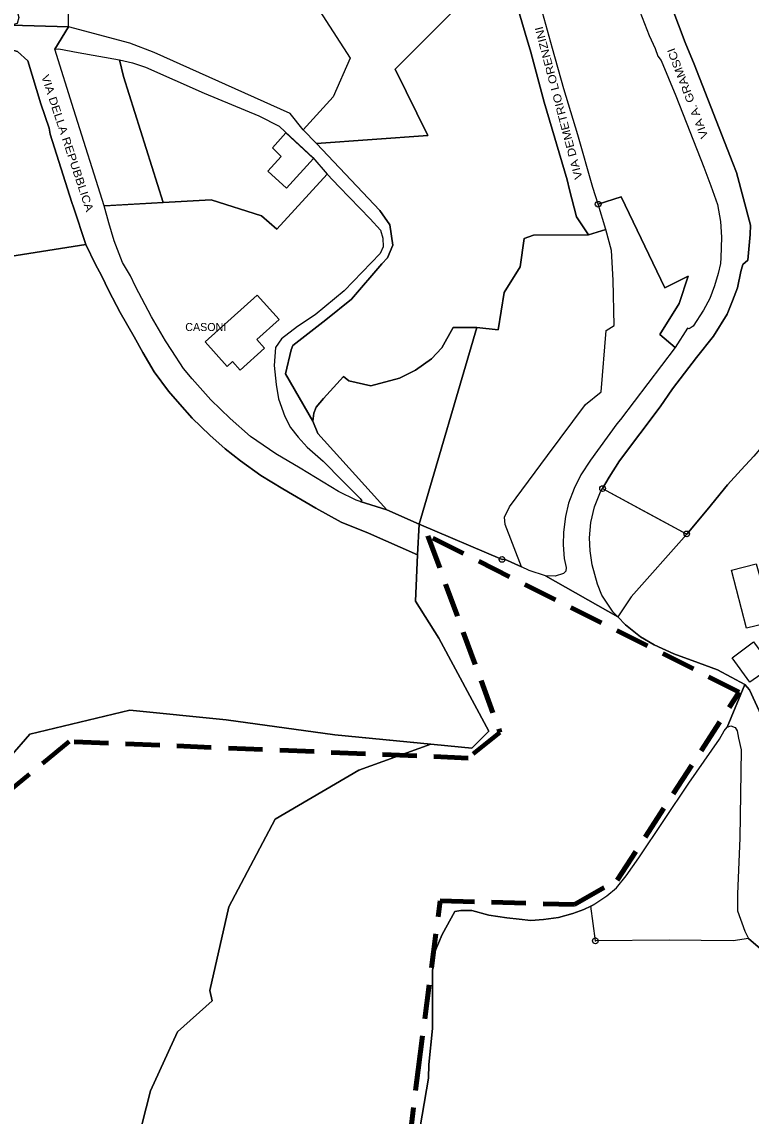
# Model space of a CAD drawing. Extents: x 654952 to 658955, y 890426 to 894481.
# Drawn here: x 657629.2 to 657884.3, y 891148.5 to 891531.5 of the extents above; entities that cross this region are included whole.
import ezdxf

# ---------------------------------------------------------------- set-up
doc = ezdxf.new("R2010")
doc.units = 0
doc.header["$LTSCALE"] = 4
doc.header["$PDMODE"] = 32
doc.header["$PDSIZE"] = 2
doc.linetypes.add('MEDIUM_DASHED', pattern=[4.5, 3, -1.5])
for name, color, linetype, lineweight in [('1', 7, 'Continuous', 25), ('11', 7, 'Continuous', 25), ('14', 7, 'Continuous', 25), ('17', 7, 'Continuous', 25), ('19', 7, 'Continuous', 25), ('36', 7, 'Continuous', 25), ('4', 7, 'Continuous', 25), ('5', 7, 'Continuous', 25), ('55', 7, 'Continuous', 25), ('56', 7, 'Continuous', 25), ('6', 7, 'Continuous', 25), ('7', 7, 'MEDIUM_DASHED', 100), ('9', 7, 'Continuous', 25)]:
    doc.layers.add(name, color=color, linetype=linetype, lineweight=lineweight)
doc.layers.add('58', color=7, linetype='Continuous')

msp = doc.modelspace()

# ---------------------------------------------------------------- linework, layer by layer
at = {"layer": '1'}
msp.add_line((657695.42, 891469.27), (657678.6, 891468.31), dxfattribs=at)
for points in [[(657678.6, 891468.31), (657664.76, 891512.47), (657663.34, 891518.26)], [(657663.34, 891518.26), (657667.91, 891517.26), (657672.42, 891515.71), (657692.92, 891506.62), (657712.15, 891498.68), (657719.21, 891495.02), (657721.27, 891493.05), (657730.99, 891484.02), (657736.01, 891478.21), (657718.39, 891458.96)], [(657953.49, 891476.31), (657955.21, 891471.7), (657956.89, 891451.72), (657957.48, 891438.11), (657957.77, 891432.29), (657956.5, 891430.66), (657954.45, 891430.79), (657949.69, 891426.24), (657930.35, 891404.21), (657925.88, 891406.29), (657918.64, 891416.53), (657907.61, 891404.82), (657900.08, 891396.93), (657885.32, 891379.52), (657880.83, 891374.69), (657876.1, 891369.48), (657868.99, 891360.8), (657861.85, 891352.23), (657842.43, 891330.3), (657837.7, 891323.26)], [(657718.39, 891458.96), (657713.01, 891463.69), (657695.42, 891469.27)], [(657837.7, 891323.26), (657840.4, 891320.51), (657845.62, 891316.26), (657850.47, 891313.45), (657857.34, 891310.34), (657865.89, 891307.18), (657872.64, 891304.78), (657879.11, 891301.28), (657882.13, 891299.62), (657883.82, 891297.74), (657888.48, 891287.53), (657889.08, 891285.16), (657888.12, 891269.81), (657887.77, 891267.8)]]:
    msp.add_lwpolyline(points, dxfattribs=at)
msp.add_lwpolyline([(657721.5, 891492.72), (657716.87, 891487.48), (657719.94, 891484.48), (657715.24, 891479.24), (657721.75, 891473.36), (657731.22, 891483.7)], close=True, dxfattribs=at)
at = {"layer": '11'}
for points in [[(657612.44, 891525.06), (657603.45, 891527.64), (657600.85, 891527.58), (657598.53, 891526.44), (657597.01, 891523.81), (657596.57, 891520.94), (657596.5, 891516.66), (657597.25, 891510.92), (657599.18, 891502.46), (657600, 891499.29), (657601.87, 891493.71), (657611.58, 891461.59), (657620.6, 891460.91), (657620.37, 891448.67), (657651.61, 891453.59), (657647.29, 891466.67), (657646.69, 891468.3), (657639.1, 891492.2), (657638.77, 891494.29)], [(657638.77, 891494.29), (657635.87, 891502.88), (657631.27, 891517.96), (657627.62, 891521.13), (657622.31, 891522.75), (657620.45, 891522.84), (657612.44, 891525.06)], [(657640.71, 891522.01), (657642.07, 891522.16), (657648.91, 891520.86), (657663.34, 891518.26), (657664.76, 891512.47), (657678.6, 891468.31)], [(657658, 891467.15), (657647.42, 891500.81), (657640.71, 891522.01)], [(657678.6, 891468.31), (657658.26, 891467.15), (657658, 891467.15)]]:
    msp.add_lwpolyline(points, dxfattribs=at)
at = {"layer": '14'}
for points in [[(657837.33, 891390.89), (657828.1, 891378.09), (657824.73, 891372.99), (657822.45, 891368.23), (657820.5, 891363.13), (657819.46, 891358.45), (657818.73, 891352.95), (657818.56, 891348.53), (657818.99, 891343.7), (657819.66, 891340.59), (657819.55, 891339.33), (657818.74, 891338.41), (657815.82, 891337.47), (657812.41, 891337.65), (657806.68, 891339.49), (657804.03, 891340.81), (657798.28, 891355.63), (657798.1, 891358.12), (657799.85, 891361.84), (657813.15, 891379.75), (657826.44, 891397.66), (657831.94, 891402.03), (657833.69, 891423.53), (657836.43, 891425.22), (657836.13, 891441.12), (657835.52, 891451.47), (657833.46, 891458.9), (657830.83, 891467.72), (657838.86, 891470.29)], [(657838.86, 891470.29), (657854.12, 891438.49), (657862.38, 891442.49), (657859.23, 891433), (657852.43, 891422.09), (657857.74, 891417.62)], [(657732.71, 891387.43), (657756.87, 891360.69), (657768.23, 891355.67), (657788.41, 891424.54), (657780.06, 891424.61), (657776.15, 891417.43), (657772.53, 891413.57), (657766.95, 891409.66), (657761.31, 891406.85), (657751.33, 891404.18), (657743.62, 891405.87), (657741.74, 891407.44), (657734.77, 891399.71), (657732.17, 891396.67)], [(657857.74, 891417.62), (657838.64, 891392.42), (657837.33, 891390.89)], [(657732.17, 891396.67), (657731.39, 891394.6), (657731.05, 891391.77), (657732.71, 891387.43)], [(657837.7, 891323.26), (657836.03, 891324.96), (657832.15, 891330.9), (657830.61, 891334.67), (657828.77, 891341.5), (657828.05, 891346.42), (657827.85, 891350.89), (657828.26, 891356.29), (657829.61, 891361.79), (657831.71, 891367), (657832.38, 891368.18), (657832.38, 891368.18), (657832.38, 891368.18)], [(657832.38, 891368.18), (657861.84, 891352.23), (657842.43, 891330.3), (657837.7, 891323.26)]]:
    msp.add_lwpolyline(points, dxfattribs=at)
msp.add_point((657832.38, 891368.18), dxfattribs=at)
at = {"layer": '17'}
for points in [[(657705.65, 891377.93), (657700.33, 891382.14), (657694.9, 891386.88), (657688.82, 891392.85), (657684.49, 891397.73), (657680.55, 891402.29), (657675.43, 891409.07), (657671.46, 891415.82), (657668.44, 891421.27), (657663.6, 891429.87), (657659.65, 891437.35), (657657.03, 891442.79), (657654.91, 891446.58), (657651.61, 891453.59), (657620.37, 891448.67)], [(657740.89, 891356.42), (657731.99, 891361.32), (657720.49, 891368.11), (657712.76, 891372.81), (657705.65, 891377.93)], [(657767.62, 891344.98), (657750.45, 891352.53), (657740.89, 891356.42)], [(657792.59, 891283.23), (657775.12, 891315.82), (657766.9, 891328.81), (657767.62, 891344.98)], [(657596.3, 891243.96), (657611.19, 891258.39), (657631.96, 891282.25), (657666.91, 891290.65), (657700.64, 891287.28), (657738.71, 891281.98), (657786.67, 891277.37), (657792.59, 891283.23)], [(657828.3, 891222.06), (657825.84, 891220.8), (657822, 891219.43), (657816.91, 891218.09), (657811.69, 891217.3), (657807.28, 891217.04), (657803.24, 891217.41), (657798.9, 891217.87), (657792.58, 891218.87), (657786.68, 891220.44), (657782.73, 891220.53), (657780.73, 891220.2), (657776.21, 891212.12), (657773.74, 891205.98), (657772.9, 891199.43), (657772.91, 891189.31), (657772.9, 891179.23), (657771.63, 891166.54)], [(657978.08, 891161.76), (657973.4, 891164.86), (657942.34, 891177.94), (657929.71, 891182.26), (657918.26, 891185.94), (657898.29, 891198.03), (657883.47, 891210.7), (657878.12, 891209.84), (657855.72, 891210.15), (657829.85, 891209.87), (657828.3, 891222.06)], [(657771.63, 891166.54), (657771.43, 891161.8), (657764.73, 891122.3), (657763.68, 891111.38), (657763.53, 891106.1), (657763.43, 891100.8), (657768.13, 891099.3), (657782.33, 891120.1), (657795.53, 891115.7), (657795.53, 891107.6), (657797.23, 891100.8), (657800.42, 891094.89), (657825.42, 891111.79)]]:
    msp.add_lwpolyline(points, dxfattribs=at)
at = {"layer": '19'}
msp.add_lwpolyline([(657734.55, 891533.67), (657744.04, 891518.8), (657738.12, 891505.34), (657727.6, 891493.76), (657732.33, 891489.03), (657771.18, 891491.81), (657759.86, 891514.99), (657780.86, 891536.17)], dxfattribs=at)
at = {"layer": '36'}
for points in [[(657538.66, 891118.94), (657535.96, 891111.27), (657548.07, 891109), (657569.02, 891094.82), (657581.96, 891081.61), (657590.87, 891070.28), (657618.73, 891081.89), (657637.72, 891085.14), (657672.85, 891085.89), (657670.36, 891103.93), (657668.28, 891134.03), (657674.22, 891157.35), (657683.59, 891178.05), (657695.83, 891188.86), (657694.99, 891192.51), (657701.57, 891221.76), (657717.86, 891252.48), (657747.12, 891269.62), (657772.31, 891278.75), (657738.71, 891281.98), (657700.64, 891287.28), (657666.91, 891290.65), (657631.96, 891282.25)], [(657631.96, 891282.25), (657611.19, 891258.39), (657596.3, 891243.96)]]:
    msp.add_lwpolyline(points, dxfattribs=at)
at = {"layer": '4'}
for points in [[(657886.17, 891341.82), (657891.92, 891321.58), (657882.74, 891319.3), (657877.46, 891339.66)], [(657883.88, 891300.46), (657877.67, 891308.94), (657885.2, 891314.52), (657891.55, 891305.84)]]:
    msp.add_lwpolyline(points, close=True, dxfattribs=at)
at = {"layer": '5'}
msp.add_line((657721.5, 891492.72), (657730.94, 891483.96), dxfattribs=at)
for points in [[(657627.6, 891534.79), (657628.17, 891533.07), (657627.52, 891531), (657625.45, 891530.42), (657645.47, 891529.84), (657645.56, 891536.63), (657633.9, 891561.11), (657628.36, 891558.61), (657626.93, 891566.36), (657626.93, 891573.49), (657627.68, 891583.11), (657629.3, 891591.67), (657631.12, 891596.05), (657640, 891619.78), (657641.69, 891619.02), (657654.9, 891646.35)], [(657830.83, 891467.72), (657829.01, 891473.58), (657823.72, 891491.98), (657818.84, 891508.15), (657814.86, 891522.18), (657811.39, 891534.78), (657805.15, 891557.48), (657792.14, 891573.58)], [(657798.92, 891550.19), (657801.57, 891540.46), (657805.28, 891527.54), (657807.3, 891520.91), (657811.96, 891503.42), (657819.94, 891476.27), (657820.8, 891472.78), (657823.22, 891463.27), (657827.48, 891457.04), (657833.46, 891458.9), (657830.83, 891467.72)], [(657658, 891467.15), (657647.42, 891500.81), (657640.71, 891522.01), (657645.47, 891529.84), (657625.45, 891530.42)], [(657723.43, 891416.77), (657723.98, 891418.22), (657735.5, 891427.3), (657744.48, 891434.54), (657755.13, 891446.87), (657757.14, 891448.91), (657758.94, 891453.37), (657757.95, 891460.5), (657754.48, 891465.47), (657732.33, 891489.03), (657727.6, 891493.76), (657723.06, 891499.45), (657675.43, 891520.8), (657666.96, 891524.08), (657645.47, 891529.84), (657640.71, 891522.01)], [(657620.45, 891522.84), (657622.31, 891522.75), (657627.62, 891521.13), (657631.27, 891517.96), (657635.87, 891502.88), (657638.77, 891494.29), (657639.1, 891492.2), (657646.69, 891468.3), (657647.29, 891466.67), (657651.61, 891453.59), (657654.91, 891446.58)], [(657640.71, 891522.01), (657642.07, 891522.16), (657648.91, 891520.86), (657663.34, 891518.26)], [(657663.34, 891518.26), (657667.91, 891517.26), (657672.42, 891515.71), (657692.92, 891506.62), (657712.15, 891498.68), (657719.21, 891495.02), (657721.27, 891493.05), (657721.56, 891492.78)], [(657730.99, 891484.02), (657736.01, 891478.21), (657740.23, 891473.84)], [(657740.23, 891473.84), (657751.11, 891462.61), (657754.72, 891458.6), (657755.44, 891455.79), (657755.56, 891452.84), (657754.61, 891450.49), (657741.93, 891437.43)], [(657667.21, 891442.61), (657664.38, 891447.34), (657661.43, 891454.89), (657659.58, 891461.21), (657658, 891467.15)], [(657654.91, 891446.58), (657657.03, 891442.79), (657659.65, 891437.35), (657663.6, 891429.87), (657668.44, 891421.27), (657671.46, 891415.82), (657675.43, 891409.07), (657680.55, 891402.29), (657684.49, 891397.73), (657688.82, 891392.85), (657694.9, 891386.88), (657700.33, 891382.14), (657705.65, 891377.93), (657712.76, 891372.81)], [(657747.59, 891363.7), (657746.2, 891364.17), (657740.02, 891367.13), (657726.57, 891375.29), (657718.01, 891380.36), (657709.23, 891386.47), (657702.08, 891392.7), (657695.28, 891399.3), (657688.74, 891406.6), (657685.77, 891410.23), (657681.61, 891416.46), (657679.49, 891419.91), (657674.58, 891428.32), (657668.92, 891438.97), (657667.21, 891442.61)], [(657741.93, 891437.43), (657731.81, 891429.01), (657725.59, 891424.93), (657720.02, 891420.57), (657717.93, 891417.51), (657717.48, 891411.3), (657718.12, 891404.56), (657719, 891399.63), (657721.17, 891393.38)], [(657721.17, 891393.38), (657723.19, 891389.61), (657725.84, 891386.21), (657729.07, 891382.69), (657734.59, 891377.73), (657741.37, 891370.9), (657747.6, 891364.69), (657748.19, 891363.92), (657747.59, 891363.7), (657756.87, 891360.69), (657732.71, 891387.43), (657731.05, 891391.77), (657721.38, 891408.35), (657723.43, 891416.77)], [(657712.76, 891372.81), (657720.49, 891368.11), (657731.99, 891361.32), (657740.89, 891356.42)], [(657740.89, 891356.42), (657750.45, 891352.53), (657767.62, 891344.98), (657768.23, 891355.67), (657756.87, 891360.69), (657747.59, 891363.7)], [(657887.64, 891240.59), (657887.66, 891246.01), (657887.77, 891267.8), (657888.12, 891269.81), (657889.08, 891285.16), (657888.48, 891287.53), (657883.82, 891297.74), (657882.13, 891299.62), (657875.99, 891284.64)], [(657875.99, 891284.64), (657877.23, 891285.16), (657878.78, 891284.6), (657879.48, 891283.39), (657879.95, 891280.84), (657880.87, 891276.71), (657880.4, 891245.81), (657879.6, 891226.27), (657879.6, 891220.39), (657882.11, 891213.26), (657883.47, 891210.7), (657898.29, 891198.03)]]:
    msp.add_lwpolyline(points, dxfattribs=at)
at = {"layer": '55'}
for points in [[(657953.49, 891476.31), (657955.21, 891471.7), (657956.89, 891451.72), (657957.48, 891438.11), (657957.77, 891432.29), (657956.5, 891430.66), (657954.45, 891430.79), (657949.69, 891426.24), (657930.35, 891404.21), (657925.88, 891406.29), (657918.64, 891416.53), (657907.61, 891404.82), (657900.08, 891396.93), (657885.32, 891379.52), (657880.83, 891374.69), (657876.1, 891369.48), (657868.99, 891360.8), (657861.85, 891352.23), (657842.43, 891330.3), (657837.7, 891323.26)], [(657837.7, 891323.26), (657840.4, 891320.51), (657845.62, 891316.26), (657850.47, 891313.45), (657857.34, 891310.34), (657865.89, 891307.18)], [(657865.89, 891307.18), (657872.64, 891304.78), (657879.11, 891301.28), (657882.13, 891299.62), (657883.82, 891297.74), (657888.48, 891287.53), (657889.08, 891285.16), (657888.12, 891269.81), (657887.77, 891267.8)]]:
    msp.add_lwpolyline(points, dxfattribs=at)
at = {"layer": '56'}
for points in [[(657798.08, 891343.45), (657797.19, 891343.4), (657768.23, 891355.67), (657767.62, 891344.98), (657766.9, 891328.81)], [(657828.3, 891222.06), (657829.65, 891222.78), (657833.85, 891225.67), (657837.28, 891228.45), (657840.61, 891232.65), (657845.1, 891238.91), (657862.51, 891265.03), (657873.31, 891280.49), (657874.98, 891283.37), (657875.99, 891284.64), (657882.13, 891299.62), (657872.64, 891304.78), (657865.89, 891307.18), (657857.34, 891310.34), (657850.47, 891313.45), (657845.62, 891316.26), (657840.4, 891320.51), (657837.7, 891323.26), (657812.41, 891337.65), (657806.68, 891339.49), (657804.03, 891340.81), (657798.08, 891343.45)], [(657766.9, 891328.81), (657775.12, 891315.82), (657792.59, 891283.23), (657786.67, 891277.37), (657772.31, 891278.75), (657747.12, 891269.62), (657717.86, 891252.48), (657701.57, 891221.76), (657694.99, 891192.51), (657695.83, 891188.86), (657683.59, 891178.05), (657674.22, 891157.35), (657668.28, 891134.03)], [(657776.76, 891111.93), (657768.13, 891099.3), (657763.43, 891100.8), (657763.53, 891106.1), (657763.68, 891111.38), (657764.73, 891122.3), (657771.43, 891161.8), (657771.63, 891166.54), (657772.9, 891179.23), (657772.91, 891189.31), (657772.9, 891199.43), (657773.74, 891205.98), (657776.21, 891212.12), (657780.73, 891220.2)], [(657780.73, 891220.2), (657782.73, 891220.53), (657786.68, 891220.44), (657792.58, 891218.87), (657798.9, 891217.87), (657803.24, 891217.41), (657807.28, 891217.04), (657811.69, 891217.3), (657816.91, 891218.09), (657822, 891219.43), (657825.84, 891220.8), (657828.3, 891222.06)]]:
    msp.add_lwpolyline(points, dxfattribs=at)
at = {"layer": '6'}
msp.add_lwpolyline([(657701.01, 891410.96), (657693.31, 891419.5), (657711.51, 891435.91), (657719.21, 891427.37), (657711.41, 891420.34), (657714.09, 891417.37), (657705.55, 891409.67), (657702.87, 891412.64)], close=True, dxfattribs=at)
at = {"layer": '7'}
msp.add_lwpolyline([(657758.18, 891086.01), (657767.85, 891164.67), (657775.55, 891223.85), (657822.54, 891222.57), (657837.5, 891231.12), (657880.22, 891296.95), (657771.27, 891351.67), (657796.48, 891282.84), (657785.37, 891273.87), (657645.7, 891279.64), (657577.41, 891223.2), (657525.69, 891246.07), (657466.47, 891318.42), (657388.34, 891335.24), (657356.54, 891378.41), (657379.71, 891383.41), (657362.45, 891431.59), (657340.55, 891496.17), (657245.72, 891490.19), (657147.58, 891653.01), (657241.87, 891677.78), (657326.96, 891719.28)], dxfattribs=at)
at = {"layer": '9'}
for points in [[(657856.8, 891403.11), (657865.28, 891414.06), (657871.15, 891421.56), (657876, 891429.27), (657877.81, 891433.86), (657879.54, 891438.46), (657880.8, 891444.18), (657881.44, 891446.67), (657883.26, 891448.13), (657883.98, 891457.09), (657884.1, 891460.34), (657879.26, 891478.81), (657877.96, 891482.09), (657864.43, 891516.77), (657861.27, 891524.29), (657852.3, 891548.25), (657844.78, 891563.7), (657843.48, 891569.42), (657833.59, 891594.22), (657821.32, 891624.99)], [(657805.15, 891557.48), (657797.89, 891583.73), (657795.1, 891593.25), (657793.26, 891603.11), (657793.15, 891607.22), (657795.07, 891612.02), (657796.86, 891613.55), (657802.31, 891616.15), (657802.56, 891615.64), (657807.54, 891618.24), (657809.29, 891619.09), (657811.32, 891619), (657812.36, 891617.17), (657820.46, 891599.62), (657823.4, 891592.46), (657830.88, 891573.05), (657832.38, 891568.94), (657848.72, 891526.75), (657850.81, 891522.18), (657851.67, 891519.51), (657852.88, 891517.99)], [(657715.62, 891613.72), (657721.93, 891602.67), (657731.8, 891584.3), (657743.68, 891572.55), (657754.8, 891561.49), (657780.86, 891536.17), (657759.86, 891514.99), (657771.18, 891491.81), (657732.33, 891489.03), (657754.48, 891465.47), (657757.95, 891460.5), (657758.94, 891453.37), (657757.14, 891448.91), (657755.13, 891446.87)], [(657833.59, 891594.22), (657843.48, 891569.42), (657844.78, 891563.7), (657852.3, 891548.25), (657861.27, 891524.29), (657864.43, 891516.77), (657877.96, 891482.09), (657879.26, 891478.81), (657884.1, 891460.34), (657883.98, 891457.09), (657883.26, 891448.13)], [(657689.24, 891586.11), (657682.3, 891570.49), (657684.55, 891562.67), (657730.99, 891539.3), (657734.55, 891533.67), (657744.04, 891518.8), (657738.12, 891505.34), (657727.6, 891493.76), (657723.06, 891499.45), (657675.43, 891520.8), (657666.96, 891524.08), (657645.47, 891529.84), (657645.56, 891536.63), (657633.9, 891561.11), (657628.36, 891558.61), (657626.93, 891566.36), (657626.93, 891573.49)], [(657832.38, 891568.94), (657848.72, 891526.75), (657850.81, 891522.18), (657851.67, 891519.51), (657852.88, 891517.99)], [(657820.8, 891472.78), (657819.94, 891476.27), (657811.96, 891503.42), (657807.3, 891520.91), (657805.28, 891527.54), (657801.57, 891540.46), (657798.92, 891550.19), (657798.18, 891552.16)], [(657830.83, 891467.72), (657830.83, 891467.72), (657829.01, 891473.58), (657823.72, 891491.98), (657818.84, 891508.15), (657814.86, 891522.18), (657811.39, 891534.78)], [(657852.88, 891517.99), (657858.05, 891505.71), (657867.86, 891480.72), (657870.22, 891474.11), (657872.59, 891467.68), (657873.66, 891461.69), (657874.04, 891456.13), (657873.73, 891448.97)], [(657852.88, 891517.99), (657858.05, 891505.71), (657867.86, 891480.72), (657870.22, 891474.11), (657872.59, 891467.68), (657873.66, 891461.69), (657874.04, 891456.13), (657873.73, 891448.97)], [(657718.39, 891458.96), (657736.01, 891478.21), (657740.23, 891473.84)], [(657740.23, 891473.84), (657751.11, 891462.61), (657754.72, 891458.6), (657755.44, 891455.79), (657755.56, 891452.84), (657754.61, 891450.49), (657741.93, 891437.43)], [(657788.41, 891424.54), (657795.89, 891423.74), (657798, 891436.86), (657803.56, 891445.82), (657804.97, 891455.7), (657808.19, 891456.89), (657827.48, 891457.04), (657823.22, 891463.27), (657820.8, 891472.78)], [(657658, 891467.15), (657678.6, 891468.31), (657695.42, 891469.27)], [(657695.42, 891469.27), (657713.01, 891463.69), (657718.39, 891458.96)], [(657857.74, 891417.62), (657852.43, 891422.09), (657859.23, 891433), (657862.38, 891442.49), (657854.12, 891438.49), (657838.86, 891470.29), (657830.83, 891467.72)], [(657667.21, 891442.61), (657664.38, 891447.34), (657661.43, 891454.89), (657659.58, 891461.21), (657658, 891467.15)], [(657827.48, 891457.04), (657808.19, 891456.89), (657804.97, 891455.7), (657803.56, 891445.82), (657798, 891436.86), (657795.89, 891423.74), (657788.41, 891424.54), (657768.23, 891355.67), (657797.19, 891343.4)], [(657797.19, 891343.4), (657798.08, 891343.45), (657804.03, 891340.81), (657798.28, 891355.63), (657798.1, 891358.12), (657799.85, 891361.84), (657813.15, 891379.75), (657826.44, 891397.66), (657831.94, 891402.03), (657833.69, 891423.53), (657836.43, 891425.22), (657836.13, 891441.12), (657835.52, 891451.47), (657833.46, 891458.9), (657827.48, 891457.04)], [(657873.73, 891448.97), (657873.6, 891446.92), (657872.82, 891443.48), (657871.52, 891439.13), (657869.88, 891434.67), (657867.75, 891430.63), (657864.04, 891425.09), (657862.7, 891424.09), (657862.11, 891424.32), (657857.74, 891417.62), (657838.64, 891392.42), (657837.33, 891390.89)], [(657873.73, 891448.97), (657873.6, 891446.92), (657872.82, 891443.48), (657871.52, 891439.13), (657869.88, 891434.67), (657867.75, 891430.63), (657864.04, 891425.09), (657862.7, 891424.09), (657862.11, 891424.32), (657857.74, 891417.62)], [(657755.13, 891446.87), (657744.48, 891434.54), (657735.5, 891427.3), (657723.98, 891418.22), (657723.43, 891416.77), (657721.38, 891408.35)], [(657883.26, 891448.13), (657881.44, 891446.67), (657880.8, 891444.18), (657879.54, 891438.46), (657877.81, 891433.86), (657876, 891429.27), (657871.15, 891421.56), (657865.28, 891414.06), (657856.8, 891403.11), (657852.49, 891396.84)], [(657741.93, 891437.43), (657731.81, 891429.01), (657725.59, 891424.93), (657720.02, 891420.57), (657717.93, 891417.51), (657717.48, 891411.3), (657718.12, 891404.56), (657719, 891399.63), (657721.17, 891393.38), (657723.19, 891389.61), (657725.84, 891386.21), (657729.07, 891382.69), (657734.59, 891377.73), (657741.37, 891370.9), (657747.6, 891364.69), (657748.19, 891363.92), (657747.59, 891363.7), (657746.2, 891364.17), (657740.02, 891367.13), (657726.57, 891375.29), (657718.01, 891380.36), (657709.23, 891386.47), (657702.08, 891392.7), (657695.28, 891399.3), (657688.74, 891406.6), (657685.77, 891410.23), (657681.61, 891416.46), (657679.49, 891419.91), (657674.58, 891428.32), (657668.92, 891438.97), (657667.21, 891442.61)], [(657731.39, 891394.6), (657732.17, 891396.67), (657734.77, 891399.71), (657741.74, 891407.44), (657743.62, 891405.87), (657751.33, 891404.18), (657761.31, 891406.85), (657766.95, 891409.66), (657772.53, 891413.57), (657776.15, 891417.43), (657780.06, 891424.61), (657788.41, 891424.54)], [(657721.38, 891408.35), (657731.05, 891391.77), (657731.39, 891394.6)], [(657832.38, 891368.18), (657834.67, 891372.19), (657838.28, 891377.92), (657852.49, 891396.84), (657856.8, 891403.11)], [(657852.49, 891396.84), (657838.28, 891377.92), (657834.67, 891372.19), (657832.38, 891368.18), (657847.11, 891360.21), (657861.84, 891352.23), (657861.84, 891352.23), (657861.84, 891352.23), (657861.84, 891352.23), (657861.84, 891352.23), (657861.84, 891352.23), (657861.84, 891352.23), (657861.84, 891352.23), (657868.99, 891360.8), (657876.1, 891369.48), (657880.82, 891374.69), (657885.31, 891379.52)], [(657837.33, 891390.89), (657828.1, 891378.09), (657824.73, 891372.99)], [(657824.73, 891372.99), (657822.45, 891368.23), (657820.5, 891363.13), (657819.46, 891358.45), (657818.73, 891352.95), (657818.56, 891348.53), (657818.99, 891343.7), (657819.66, 891340.59), (657819.55, 891339.33), (657818.74, 891338.41), (657815.82, 891337.47), (657812.41, 891337.65), (657837.7, 891323.26)], [(657837.7, 891323.26), (657836.03, 891324.96), (657832.15, 891330.9), (657830.61, 891334.67), (657828.77, 891341.5), (657828.05, 891346.42), (657827.85, 891350.89), (657828.26, 891356.29), (657829.61, 891361.79), (657831.71, 891367), (657832.38, 891368.18)], [(657829.65, 891222.78), (657833.85, 891225.67), (657837.28, 891228.45), (657840.61, 891232.65), (657845.1, 891238.91), (657862.51, 891265.03), (657873.31, 891280.49), (657874.98, 891283.37), (657875.99, 891284.64), (657877.23, 891285.16), (657878.78, 891284.6), (657879.48, 891283.39), (657879.95, 891280.84), (657880.87, 891276.71), (657880.4, 891245.81), (657879.6, 891226.27), (657879.6, 891220.39), (657882.11, 891213.26), (657883.47, 891210.7), (657878.12, 891209.84), (657855.72, 891210.15), (657829.85, 891209.87)], [(657829.85, 891209.87), (657828.3, 891222.06), (657829.65, 891222.78)]]:
    msp.add_lwpolyline(points, dxfattribs=at)
for p in [(657830.83, 891467.72), (657861.81, 891352.33), (657797.19, 891343.4), (657829.85, 891209.87)]:
    msp.add_point(p, dxfattribs=at)

# ---------------------------------------------------------------- texts
at = {"layer": '58', "width": 1.15}
for s, height, rotation, p in [('VIA DEMETRIO LORENZINI', 2.804, 104.772, (657825.38, 891476.88)), ('VIA A. GRAMSCI', 2.802, 110.911, (657869.45, 891491.37)), ('VIA DELLA REPUBBLICA', 2.798, 288.309, (657635.93, 891512.52))]:
    msp.add_text(s, height=height, rotation=rotation, dxfattribs=at).set_placement(p)
at = {"layer": '58'}
msp.add_text('CASONI', height=2.801, dxfattribs=at).set_placement((657686.36, 891423.34))

doc.saveas('drawing.dxf')
